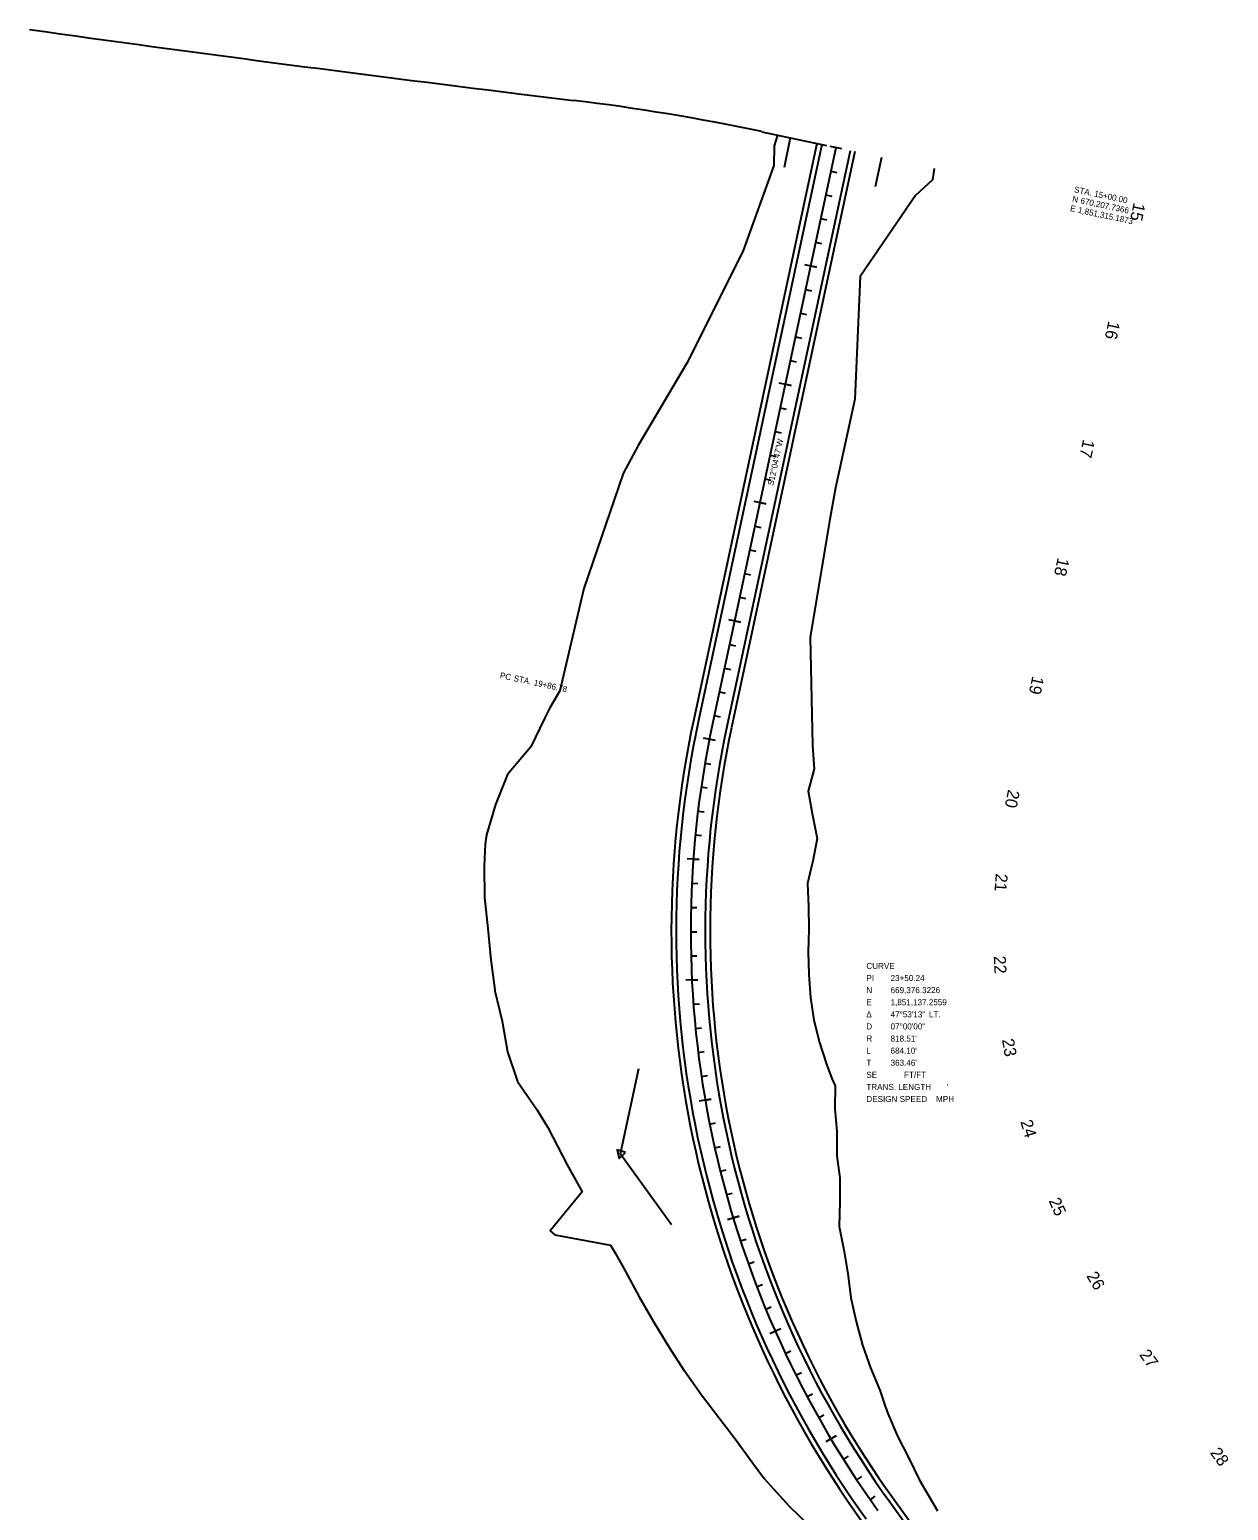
# Model space of a CAD drawing. Extents: x 1849567 to 1851966, y 666813 to 670457.
# Drawn here: x 1850649 to 1851639, y 669082 to 670305 of the extents above; entities that cross this region are included whole.
import ezdxf

# ---------------------------------------------------------------- set-up
doc = ezdxf.new("R2010")
doc.units = 0
for name, color, linetype in [('_CIVIL_CONSTRUCTION', 7, 'Continuous'), ('Default', 7, 'Continuous'), ('DES - CL - Proposed', 7, 'Continuous'), ('DES - CL - Proposed Curve Text', 7, 'Continuous'), ('DES - CL - Proposed Text', 7, 'Continuous'), ('DES - CL - Proposed Text - Large', 7, 'Continuous'), ('DES - CL - Proposed Text - Small', 7, 'Continuous'), ('DES - MODEL - Lines - Cut Slopes', 7, 'Continuous'), ('DES - MODEL - Lines - Ditch Centerline', 7, 'Continuous'), ('DES - MODEL - Lines - Pavement Edge', 7, 'Continuous'), ('DES - MODEL - Lines - Shoulder Edge', 7, 'Continuous')]:
    doc.layers.add(name, color=color, linetype=linetype)

msp = doc.modelspace()

# ---------------------------------------------------------------- linework, layer by layer
at = {"layer": '_CIVIL_CONSTRUCTION'}
msp.add_line((1851315.2, 670207.7), (1851213.3, 669731.7), dxfattribs=at)
msp.add_arc((1852013.7, 669560.4), 818.5, 167.9203, 215.8071, dxfattribs=at)
at = {"layer": 'Default'}
for p, q in [((1851053.3, 670252.2), (1851098.4, 670246.7)), ((1851253.9, 670220.9), (1851307.4, 670209.6)), ((1851315.2, 670207.7), (1851213.3, 669731.7)), ((1851315.2, 670207.7), (1851213.3, 669731.7))]:
    msp.add_line(p, q, dxfattribs=at)
for centre, radius, start, end in [((1853826.3, 692955.2), 22871.6, 262.01516, 263.03621), ((1850876.5, 668430.2), 1830.1, 78.0988, 83.0362), ((1852013.7, 669560.4), 818.5, 167.9203, 215.8071), ((1852013.7, 669560.4), 818.5, 167.9203, 215.8071)]:
    msp.add_arc(centre, radius, start, end, dxfattribs=at)
at = {"layer": 'DES - CL - Proposed'}
for p, q in [((1851053.3, 670252.2), (1851098.4, 670246.7)), ((1851253.9, 670220.9), (1851307.4, 670209.6)), ((1851315.2, 670207.7), (1851213.3, 669731.7))]:
    msp.add_line(p, q, dxfattribs=at)
for centre, radius, start, end in [((1853826.3, 692955.2), 22871.6, 262.01516, 263.03621), ((1850876.5, 668430.2), 1830.1, 78.0988, 83.0362), ((1852013.7, 669560.4), 818.5, 167.9203, 215.8071)]:
    msp.add_arc(centre, radius, start, end, dxfattribs=at)
at = {"layer": 'DES - CL - Proposed Text'}
for q in [(1851152.3, 669446.7), (1851152.3, 669446.7), (1851137.3, 669376.3), (1851179.4, 669317.9), (1851137.3, 669376.3), (1851179.4, 669317.9)]:
    msp.add_line((1851137.3, 669376.3), q, dxfattribs=at)
msp.add_lwpolyline([(1851141.3, 669377.2), (1851134.5, 669379.4), (1851136, 669372.4)], close=True, dxfattribs=at)
msp.add_lwpolyline([(1851141.3, 669377.2), (1851134.5, 669379.4), (1851136, 669372.4)], close=True, dxfattribs=at)
at = {"layer": 'DES - CL - Proposed Text - Large'}
for p, q in [((1851320.1, 670206.7), (1851310.3, 670208.8)), ((1851320.1, 670206.7), (1851310.3, 670208.8)), ((1851294.3, 670110), (1851299.1, 670108.9)), ((1851294.3, 670110), (1851299.1, 670108.9)), ((1851273.3, 670012.2), (1851278.2, 670011.1)), ((1851273.3, 670012.2), (1851278.2, 670011.1)), ((1851252.4, 669914.4), (1851257.3, 669913.3)), ((1851252.4, 669914.4), (1851257.3, 669913.3)), ((1851231.5, 669816.6), (1851236.3, 669815.6)), ((1851231.5, 669816.6), (1851236.3, 669815.6)), ((1851215.6, 669717.8), (1851205.7, 669719.8)), ((1851215.6, 669717.8), (1851205.7, 669719.8)), ((1851197.3, 669619.7), (1851202.3, 669619.4)), ((1851197.3, 669619.7), (1851202.3, 669619.4)), ((1851196.2, 669519.8), (1851201.2, 669520.1)), ((1851196.2, 669519.8), (1851201.2, 669520.1)), ((1851207.2, 669420.5), (1851212.2, 669421.3)), ((1851207.2, 669420.5), (1851212.2, 669421.3)), ((1851230.3, 669323.2), (1851235.1, 669324.7)), ((1851230.3, 669323.2), (1851235.1, 669324.7)), ((1851269.6, 669231.6), (1851260.5, 669227.5)), ((1851269.6, 669231.6), (1851260.5, 669227.5)), ((1851311, 669140.8), (1851315.2, 669143.3)), ((1851311, 669140.8), (1851315.2, 669143.3))]:
    msp.add_line(p, q, dxfattribs=at)
at = {"layer": 'DES - CL - Proposed Text - Small'}
for p, q in [((1851320.1, 670206.7), (1851310.3, 670208.8)), ((1851320.1, 670206.7), (1851310.3, 670208.8)), ((1851311, 670188.2), (1851315.9, 670187.1)), ((1851311, 670188.2), (1851315.9, 670187.1)), ((1851306.8, 670168.6), (1851311.7, 670167.6)), ((1851306.8, 670168.6), (1851311.7, 670167.6)), ((1851302.6, 670149.1), (1851307.5, 670148)), ((1851302.6, 670149.1), (1851307.5, 670148)), ((1851298.4, 670129.5), (1851303.3, 670128.5)), ((1851298.4, 670129.5), (1851303.3, 670128.5)), ((1851299.1, 670108.9), (1851289.4, 670111)), ((1851299.1, 670108.9), (1851289.4, 670111)), ((1851290.1, 670090.4), (1851294.9, 670089.4)), ((1851290.1, 670090.4), (1851294.9, 670089.4)), ((1851285.9, 670070.8), (1851290.8, 670069.8)), ((1851285.9, 670070.8), (1851290.8, 670069.8)), ((1851281.7, 670051.3), (1851286.6, 670050.2)), ((1851281.7, 670051.3), (1851286.6, 670050.2)), ((1851277.5, 670031.7), (1851282.4, 670030.7)), ((1851277.5, 670031.7), (1851282.4, 670030.7)), ((1851278.2, 670011.1), (1851268.4, 670013.2)), ((1851278.2, 670011.1), (1851268.4, 670013.2)), ((1851269.1, 669992.6), (1851274, 669991.6)), ((1851269.1, 669992.6), (1851274, 669991.6)), ((1851265, 669973.1), (1851269.8, 669972)), ((1851265, 669973.1), (1851269.8, 669972)), ((1851260.8, 669953.5), (1851265.6, 669952.5)), ((1851260.8, 669953.5), (1851265.6, 669952.5)), ((1851256.6, 669933.9), (1851261.5, 669932.9)), ((1851256.6, 669933.9), (1851261.5, 669932.9)), ((1851257.3, 669913.3), (1851247.5, 669915.4)), ((1851257.3, 669913.3), (1851247.5, 669915.4)), ((1851248.2, 669894.8), (1851253.1, 669893.8)), ((1851248.2, 669894.8), (1851253.1, 669893.8)), ((1851244, 669875.3), (1851248.9, 669874.2)), ((1851244, 669875.3), (1851248.9, 669874.2)), ((1851239.8, 669855.7), (1851244.7, 669854.7)), ((1851239.8, 669855.7), (1851244.7, 669854.7)), ((1851235.7, 669836.2), (1851240.5, 669835.1)), ((1851235.7, 669836.2), (1851240.5, 669835.1)), ((1851236.4, 669815.5), (1851226.6, 669817.6)), ((1851236.4, 669815.5), (1851226.6, 669817.6)), ((1851227.3, 669797), (1851232.2, 669796)), ((1851227.3, 669797), (1851232.2, 669796)), ((1851223.1, 669777.5), (1851228, 669776.4)), ((1851223.1, 669777.5), (1851228, 669776.4)), ((1851218.9, 669757.9), (1851223.8, 669756.9)), ((1851218.9, 669757.9), (1851223.8, 669756.9)), ((1851214.7, 669738.4), (1851219.6, 669737.3)), ((1851214.7, 669738.4), (1851219.6, 669737.3)), ((1851215.6, 669717.8), (1851205.7, 669719.8)), ((1851215.6, 669717.8), (1851205.7, 669719.8)), ((1851207, 669699.1), (1851211.9, 669698.3)), ((1851207, 669699.1), (1851211.9, 669698.3)), ((1851203.9, 669679.4), (1851208.8, 669678.6)), ((1851203.9, 669679.4), (1851208.8, 669678.6)), ((1851201.2, 669659.5), (1851206.2, 669658.9)), ((1851201.2, 669659.5), (1851206.2, 669658.9)), ((1851199, 669639.7), (1851204, 669639.2)), ((1851199, 669639.7), (1851204, 669639.2)), ((1851202.3, 669619.4), (1851192.4, 669620.1)), ((1851202.3, 669619.4), (1851192.4, 669620.1)), ((1851196.1, 669599.8), (1851201.1, 669599.5)), ((1851196.1, 669599.8), (1851201.1, 669599.5)), ((1851195.4, 669579.8), (1851200.4, 669579.7)), ((1851195.4, 669579.8), (1851200.4, 669579.7)), ((1851195.2, 669559.8), (1851200.2, 669559.8)), ((1851195.2, 669559.8), (1851200.2, 669559.8)), ((1851195.5, 669539.8), (1851200.4, 669539.9)), ((1851195.5, 669539.8), (1851200.4, 669539.9)), ((1851201.2, 669520.1), (1851191.2, 669519.6)), ((1851201.2, 669520.1), (1851191.2, 669519.6)), ((1851197.4, 669499.8), (1851202.4, 669500.2)), ((1851197.4, 669499.8), (1851202.4, 669500.2)), ((1851199.2, 669479.9), (1851204.1, 669480.4)), ((1851199.2, 669479.9), (1851204.1, 669480.4)), ((1851201.4, 669460), (1851206.3, 669460.7)), ((1851201.4, 669460), (1851206.3, 669460.7)), ((1851204.1, 669440.2), (1851209, 669441)), ((1851204.1, 669440.2), (1851209, 669441)), ((1851212.2, 669421.3), (1851202.3, 669419.6)), ((1851212.2, 669421.3), (1851202.3, 669419.6)), ((1851210.9, 669400.8), (1851215.8, 669401.8)), ((1851210.9, 669400.8), (1851215.8, 669401.8)), ((1851215, 669381.3), (1851219.9, 669382.3)), ((1851215, 669381.3), (1851219.9, 669382.3)), ((1851219.7, 669361.8), (1851224.5, 669363)), ((1851219.7, 669361.8), (1851224.5, 669363)), ((1851224.8, 669342.5), (1851229.6, 669343.8)), ((1851224.8, 669342.5), (1851229.6, 669343.8)), ((1851235.1, 669324.7), (1851225.5, 669321.8)), ((1851235.1, 669324.7), (1851225.5, 669321.8)), ((1851236.3, 669304.2), (1851241.1, 669305.7)), ((1851236.3, 669304.2), (1851241.1, 669305.7)), ((1851242.8, 669285.3), (1851247.5, 669286.9)), ((1851242.8, 669285.3), (1851247.5, 669286.9)), ((1851249.8, 669266.5), (1851254.4, 669268.3)), ((1851249.8, 669266.5), (1851254.4, 669268.3)), ((1851257.2, 669247.9), (1851261.8, 669249.8)), ((1851257.2, 669247.9), (1851261.8, 669249.8)), ((1851269.6, 669231.6), (1851260.5, 669227.5)), ((1851269.6, 669231.6), (1851260.5, 669227.5)), ((1851273.4, 669211.3), (1851277.9, 669213.5)), ((1851273.4, 669211.3), (1851277.9, 669213.5)), ((1851282.1, 669193.4), (1851286.6, 669195.6)), ((1851282.1, 669193.4), (1851286.6, 669195.6)), ((1851291.3, 669175.6), (1851295.7, 669177.9)), ((1851291.3, 669175.6), (1851295.7, 669177.9)), ((1851300.9, 669158.1), (1851305.3, 669160.5)), ((1851300.9, 669158.1), (1851305.3, 669160.5)), ((1851315.3, 669143.3), (1851306.7, 669138.2)), ((1851315.3, 669143.3), (1851306.7, 669138.2)), ((1851321.4, 669123.7), (1851325.6, 669126.4)), ((1851321.4, 669123.7), (1851325.6, 669126.4)), ((1851332.3, 669106.9), (1851336.5, 669109.7)), ((1851332.3, 669106.9), (1851336.5, 669109.7)), ((1851343.6, 669090.4), (1851347.7, 669093.3)), ((1851343.6, 669090.4), (1851347.7, 669093.3))]:
    msp.add_line(p, q, dxfattribs=at)
at = {"layer": 'DES - MODEL - Lines - Cut Slopes'}
for points in [[(1851266.8, 670218.1), (1851264.2, 670209.1), (1851264, 670193.1), (1851238.4, 670121.9), (1851192, 670029.6), (1851151.9, 669961.5), (1851139.5, 669938.5), (1851106.9, 669843.3), (1851087.2, 669758.7), (1851078.8, 669744.8), (1851074.4, 669735.9), (1851063.1, 669712.5), (1851043.9, 669689.7), (1851034, 669665), (1851026.4, 669639.8), (1851025.5, 669632.2), (1851024.5, 669614), (1851024.9, 669588.1), (1851027.6, 669562.3), (1851030.1, 669536.6), (1851033.4, 669511.7), (1851033.4, 669511), (1851039.4, 669485.8), (1851044, 669460.6), (1851052.1, 669436), (1851068.1, 669412.9), (1851077.3, 669397.9), (1851081.3, 669389.9), (1851093.2, 669367.1), (1851105.5, 669344.8), (1851079.1, 669312.5), (1851083.1, 669309.4), (1851128.9, 669300.8), (1851133.1, 669293.8), (1851141.2, 669279.5), (1851152.5, 669258.1), (1851164.8, 669237.2), (1851177.2, 669216.7), (1851190.2, 669196.6), (1851190.3, 669196.5), (1851204, 669177.1), (1851218.4, 669158.2), (1851232.7, 669139.5), (1851246.6, 669120.7), (1851255.9, 669107.9), (1851260.8, 669102.3), (1851276.5, 669085.1), (1851293.4, 669068.9)], [(1851396.3, 670190.4), (1851395, 670181.1), (1851380.9, 670168.1), (1851335.3, 670101.2), (1851330.9, 669999.8), (1851314.7, 669926.6), (1851310.3, 669902), (1851293.8, 669803.3), (1851295.9, 669714), (1851296.7, 669701.8), (1851297.2, 669694.3), (1851292.3, 669675.8), (1851295.7, 669656.1), (1851299.7, 669636.7), (1851296.2, 669618.1), (1851294.6, 669612.7), (1851291.6, 669599.6), (1851292.4, 669580.6), (1851292.7, 669561.8), (1851292.2, 669543), (1851292.7, 669524.6), (1851292.7, 669524.1), (1851294.1, 669505.3), (1851296.8, 669486.6), (1851301.5, 669468.3), (1851307.5, 669450.2), (1851311.8, 669438.6), (1851314.5, 669432.5), (1851314.3, 669413.5), (1851315.8, 669394.7), (1851316, 669375.4), (1851316.3, 669372.3), (1851318.4, 669356.4), (1851318.5, 669349.9), (1851318.3, 669336.5), (1851317.7, 669316.1), (1851321.7, 669297), (1851325, 669277.4), (1851327.6, 669257.3), (1851327.6, 669257.2), (1851331.8, 669237.6), (1851337, 669218.2), (1851343.7, 669199.3), (1851351.3, 669180.8), (1851355.9, 669167.6), (1851358.1, 669161.6), (1851366, 669142.8), (1851375.4, 669124.8), (1851384.3, 669106.4), (1851399, 669081.1)]]:
    msp.add_lwpolyline(points, dxfattribs=at)
at = {"layer": 'DES - MODEL - Lines - Ditch Centerline'}
for p, q in [((1851277.5, 670215.8), (1851272.3, 670191.4)), ((1851352.9, 670199.7), (1851347.6, 670175.2))]:
    msp.add_line(p, q, dxfattribs=at)
at = {"layer": 'DES - MODEL - Lines - Pavement Edge'}
for p, q in [((1851303.5, 670210.2), (1851201.6, 669734.2)), ((1851326.9, 670205.2), (1851225.1, 669729.2)), ((1851359.6, 669088.6), (1851475.7, 668927.7))]:
    msp.add_line(p, q, dxfattribs=at)
for radius in [830.5, 806.5]:
    msp.add_arc((1852013.7, 669560.4), radius, 167.9203, 215.8072, dxfattribs=at)
at = {"layer": 'DES - MODEL - Lines - Shoulder Edge'}
for p, q in [((1851299.5, 670211.1), (1851197.7, 669735.1)), ((1851330.8, 670204.4), (1851229, 669728.4)), ((1851362.9, 669090.9), (1851479, 668930))]:
    msp.add_line(p, q, dxfattribs=at)
for radius in [834.5, 802.5]:
    msp.add_arc((1852013.7, 669560.4), radius, 167.9203, 215.8072, dxfattribs=at)

# ---------------------------------------------------------------- texts
at = {"layer": 'DES - CL - Proposed Curve Text'}
for s, p in [('PC', (1851037.3, 669769.4)), ('PC', (1851037.3, 669769.4)), (' STA. ', (1851046.8, 669767.4)), (' STA. ', (1851046.8, 669767.4)), ('19+86.78', (1851065.2, 669763.4)), ('19+86.78', (1851065.2, 669763.4))]:
    msp.add_text(s, height=4.98, rotation=347.9203, dxfattribs=at).set_placement(p)
for s, p in [('CURVE    ', (1851340.3, 669529)), ('CURVE    ', (1851340.3, 669529)), ('PI', (1851340.3, 669519)), ('PI', (1851340.3, 669519)), ('23+50.24', (1851360.3, 669519)), ('23+50.24', (1851360.3, 669519)), ('N', (1851340.3, 669509)), ('N', (1851340.3, 669509)), ('669,376.3226', (1851360.3, 669509)), ('669,376.3226', (1851360.3, 669509)), ('E', (1851340.3, 669499)), ('E', (1851340.3, 669499)), ('1,851,137.2559', (1851360.3, 669499)), ('1,851,137.2559', (1851360.3, 669499)), ('Δ', (1851340.3, 669489)), ('Δ', (1851340.3, 669489)), ('47°53\'13"', (1851360.3, 669489)), ('47°53\'13"', (1851360.3, 669489)), (' LT.', (1851390.2, 669489)), (' LT.', (1851390.2, 669489)), ('D', (1851340.3, 669479)), ('D', (1851340.3, 669479)), ('R', (1851340.3, 669469)), ('R', (1851340.3, 669469)), ('07°00\'00"', (1851360.3, 669479)), ('07°00\'00"', (1851360.3, 669479)), ("818.51'", (1851360.3, 669469)), ("818.51'", (1851360.3, 669469)), ('L', (1851340.3, 669459)), ('L', (1851340.3, 669459)), ("684.10'", (1851360.3, 669459)), ("684.10'", (1851360.3, 669459)), ('T', (1851340.3, 669449)), ('T', (1851340.3, 669449)), ("363.46'", (1851360.3, 669449)), ("363.46'", (1851360.3, 669449)), ('SE', (1851340.3, 669439)), ('SE', (1851340.3, 669439)), ('      FT/FT', (1851360.3, 669439)), ('      FT/FT', (1851360.3, 669439)), ("TRANS. LENGTH       '", (1851340.3, 669429)), ("TRANS. LENGTH       '", (1851340.3, 669429)), ('DESIGN SPEED    MPH', (1851340.3, 669419)), ('DESIGN SPEED    MPH', (1851340.3, 669419))]:
    msp.add_text(s, height=5, dxfattribs=at).set_placement(p)
at = {"layer": 'DES - CL - Proposed Text'}
for s, rotation, p in [('STA. ', 347.9203, (1851511.6, 670170.9)), ('STA. ', 347.9203, (1851511.6, 670170.9)), ('15+00.00', 347.9203, (1851528.1, 670167.4)), ('15+00.00', 347.9203, (1851528.1, 670167.4)), ('E ', 347.9203, (1851508.3, 670155.4)), ('E ', 347.9203, (1851508.3, 670155.4)), ('N ', 347.9203, (1851510, 670163.2)), ('N ', 347.9203, (1851510, 670163.2)), ('1,851,315.1873', 347.9203, (1851514.7, 670154)), ('1,851,315.1873', 347.9203, (1851514.7, 670154)), ('670,207.7366', 347.9203, (1851516.8, 670161.7)), ('670,207.7366', 347.9203, (1851516.8, 670161.7)), ('S12°04\'47"W', 77.9203, (1851263.5, 669928.1)), ('S12°04\'47"W', 77.9203, (1851263.5, 669928.1))]:
    msp.add_text(s, height=4.98, rotation=rotation, dxfattribs=at).set_placement(p)
at = {"layer": 'DES - CL - Proposed Text - Large'}
for s, rotation, p in [('15', 257.9203, (1851561.2, 670162.7)), ('15', 257.9203, (1851561.2, 670162.7)), ('20', 258.8454, (1851457.4, 669677.7)), ('20', 258.8454, (1851457.4, 669677.7)), ('25', 293.8455, (1851490.7, 669337.4)), ('25', 293.8455, (1851490.7, 669337.4))]:
    msp.add_text(s, height=9.96, rotation=rotation, dxfattribs=at).set_placement(p)
at = {"layer": 'DES - CL - Proposed Text - Small'}
for s, rotation, p in [('15', 257.9203, (1851561.2, 670162.7)), ('15', 257.9203, (1851561.2, 670162.7)), ('16', 257.9203, (1851540.3, 670064.9)), ('16', 257.9203, (1851540.3, 670064.9)), ('17', 257.9203, (1851519.4, 669967.1)), ('17', 257.9203, (1851519.4, 669967.1)), ('18', 257.9203, (1851498.4, 669869.3)), ('18', 257.9203, (1851498.4, 669869.3)), ('19', 257.9203, (1851477.5, 669771.5)), ('19', 257.9203, (1851477.5, 669771.5)), ('20', 258.8454, (1851457.4, 669677.7)), ('20', 258.8454, (1851457.4, 669677.7)), ('21', 265.8454, (1851447.2, 669608.1)), ('21', 265.8454, (1851447.2, 669608.1)), ('22', 272.8455, (1851445.5, 669539.6)), ('22', 272.8455, (1851445.5, 669539.6)), ('23', 279.8455, (1851452.3, 669470.5)), ('23', 279.8455, (1851452.3, 669470.5)), ('24', 286.8455, (1851467.4, 669402.8)), ('24', 286.8455, (1851467.4, 669402.8)), ('25', 293.8455, (1851490.7, 669337.4)), ('25', 293.8455, (1851490.7, 669337.4)), ('26', 300.8455, (1851521.8, 669275.3)), ('26', 300.8455, (1851521.8, 669275.3)), ('27', 305.8071, (1851565.3, 669210.2)), ('27', 305.8071, (1851565.3, 669210.2)), ('28', 305.8071, (1851623.8, 669129.1)), ('28', 305.8071, (1851623.8, 669129.1))]:
    msp.add_text(s, height=9.96, rotation=rotation, dxfattribs=at).set_placement(p)

doc.saveas('drawing.dxf')
